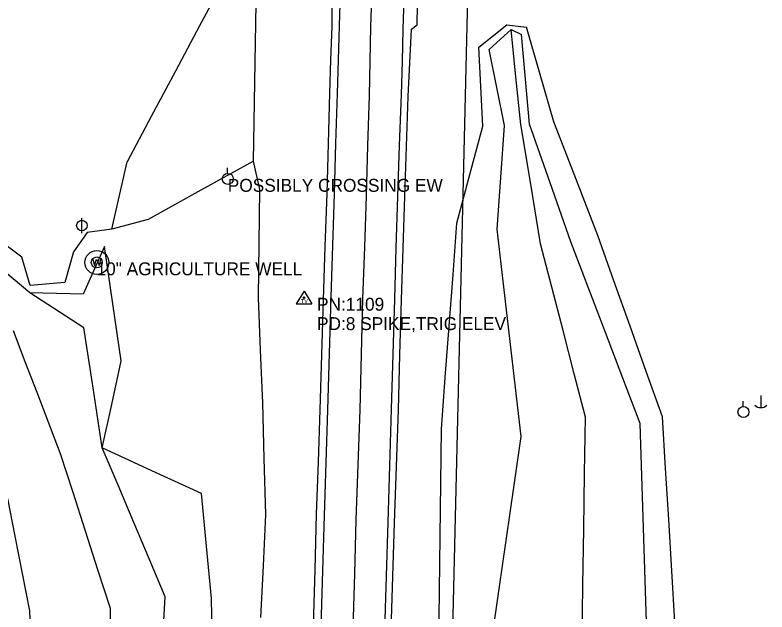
# Model space of a CAD drawing. Extents: x 1445297 to 1476720, y 2042269 to 2057889.
# Drawn here: x 1445978.9 to 1446270, y 2044535.6 to 2044766.6 of the extents above; entities that cross this region are included whole.
import ezdxf

# ---------------------------------------------------------------- set-up
doc = ezdxf.new("R2010")
doc.units = 0
for name, color, linetype in [('S_DITCHLINE', 7, 'Continuous'), ('S_EDGE_PAVEMENT', 7, 'Continuous'), ('S_PAVEMENT_CROWN', 7, 'Continuous'), ('S_SECONDARY_CTL', 7, 'Continuous'), ('S_SECONDARY_CTL_ANNOT', 7, 'Continuous'), ('S_SHOULDER', 7, 'Continuous'), ('S_STREAM', 7, 'Continuous'), ('S_UNDERGROUND_CABLE', 7, 'Continuous'), ('S_UTILITY_POLE', 7, 'Continuous'), ('S_UTILITY_POLE_ANNOT', 7, 'Continuous'), ('S_WATER_WELL', 7, 'Continuous'), ('S_WATER_WELL_ANNOT', 7, 'Continuous')]:
    doc.layers.add(name, color=color, linetype=linetype)

msp = doc.modelspace()

# ---------------------------------------------------------------- linework, layer by layer
at = {"layer": 'S_DITCHLINE'}
for points in [[(1446071.26, 2044710.05), (1446071.53, 2044725.31), (1446071.79, 2044740.57), (1446072.06, 2044755.83), (1446072.33, 2044771.09), (1446080.14, 2044771.35), (1446078.2, 2044781), (1446079.12, 2044801.93), (1446080.03, 2044822.86), (1446080.94, 2044843.78), (1446081.86, 2044864.71), (1446081.47, 2044885.83), (1446081.09, 2044906.95), (1446080.7, 2044928.07), (1446080.32, 2044949.19), (1446080.99, 2044965.26), (1446081.65, 2044981.32), (1446082.32, 2044997.38), (1446082.99, 2045013.45), (1446083.31, 2045038.44), (1446083.64, 2045063.43), (1446083.96, 2045088.42), (1446084.29, 2045113.41)], [(1446059.69, 2044779.98), (1446050.34, 2044762.42), (1446040.99, 2044744.86), (1446031.63, 2044727.3), (1446022.28, 2044709.74)], [(1446071.26, 2044710.05), (1446071.53, 2044725.31), (1446071.79, 2044740.57), (1446072.06, 2044755.83), (1446072.33, 2044771.09)], [(1446163.56, 2044524.88), (1446166.4, 2044544.53), (1446169.24, 2044564.18), (1446172.08, 2044583.82), (1446174.92, 2044603.47), (1446172.56, 2044623.53), (1446170.21, 2044643.58), (1446167.86, 2044663.63), (1446165.51, 2044683.68), (1446166.97, 2044703.75), (1446168.44, 2044723.81), (1446165.46, 2044738.52), (1446162.48, 2044753.23), (1446170.95, 2044761)], [(1446198.43, 2044524.43), (1446198.76, 2044546.08), (1446199.08, 2044567.72), (1446199.4, 2044589.36), (1446199.72, 2044611.01), (1446195.4, 2044627.76), (1446191.07, 2044644.52), (1446186.74, 2044661.28), (1446182.41, 2044678.03), (1446178.57, 2044701.13), (1446174.74, 2044724.23), (1446172.85, 2044742.61), (1446170.95, 2044761), (1446174.97, 2044759.11)], [(1446223.47, 2044527.71), (1446222.82, 2044547.92), (1446222.18, 2044568.13), (1446221.53, 2044588.33), (1446220.88, 2044608.54), (1446214.18, 2044626.13), (1446207.47, 2044643.72), (1446200.76, 2044661.31), (1446194.05, 2044678.89), (1446186.09, 2044701.62), (1446178.12, 2044724.34), (1446176.55, 2044741.73), (1446174.97, 2044759.11)], [(1446016.41, 2044683.77), (1446019.34, 2044696.75), (1446022.28, 2044709.74)], [(1446055.19, 2044527.11), (1446055, 2044540.86), (1446053.07, 2044561.15), (1446051.15, 2044581.44), (1446031.93, 2044590.26), (1446012.7, 2044599.08), (1446016.33, 2044615.93), (1446019.97, 2044632.77), (1446016.73, 2044654.89), (1446013.5, 2044677.01), (1446005.3, 2044658.54), (1445984.59, 2044659.09)], [(1446036.33, 2044527.74), (1446037.06, 2044541.54), (1446030.97, 2044555.92), (1446024.88, 2044570.31), (1446018.79, 2044584.69), (1446012.7, 2044599.08), (1446009.14, 2044622.33), (1446005.59, 2044645.59), (1445984.59, 2044659.09), (1445975.02, 2044667.24)], [(1446015.99, 2044523.36), (1446015.83, 2044536.97), (1446011.01, 2044551.93), (1446006.2, 2044566.89), (1446001.38, 2044581.86), (1445996.56, 2044596.82), (1445992.01, 2044608.7), (1445987.45, 2044620.58), (1445982.9, 2044632.46), (1445978.35, 2044644.34)], [(1445978.15, 2044367.9), (1445980.65, 2044385.13), (1445983.14, 2044402.36), (1445985.64, 2044419.58), (1445988.13, 2044436.81), (1445987.28, 2044461.63), (1445986.42, 2044486.45), (1445985.57, 2044511.27), (1445984.71, 2044536.09), (1445981.85, 2044550.56), (1445978.98, 2044565.02), (1445976.11, 2044579.49)]]:
    msp.add_lwpolyline(points, dxfattribs=at)
at = {"layer": 'S_EDGE_PAVEMENT'}
for points in [[(1446097.48, 2044530.06), (1446098.11, 2044551.51), (1446098.75, 2044572.96), (1446099.36, 2044593.42), (1446099.97, 2044613.89), (1446100.66, 2044635.63), (1446101.35, 2044657.38), (1446101.98, 2044677.4), (1446102.6, 2044697.42), (1446103.16, 2044716.83), (1446103.71, 2044736.24), (1446104.11, 2044749.29), (1446104.51, 2044762.35), (1446104.92, 2044775.04)], [(1446122.08, 2044528.6), (1446122.72, 2044549.46), (1446123.36, 2044570.32), (1446124.01, 2044592.21), (1446124.66, 2044614.1), (1446125.29, 2044635.4), (1446125.91, 2044656.7), (1446126.52, 2044676.53), (1446127.12, 2044696.37), (1446127.81, 2044716.11), (1446128.5, 2044735.85), (1446128.86, 2044748.56), (1446129.22, 2044761.27), (1446129.55, 2044772.98)], [(1446122.08, 2044528.6), (1446122.72, 2044549.46), (1446123.36, 2044570.32), (1446124.01, 2044592.21), (1446124.66, 2044614.1), (1446125.29, 2044635.4), (1446125.91, 2044656.7), (1446126.52, 2044676.53), (1446127.12, 2044696.37), (1446127.81, 2044716.11), (1446128.5, 2044735.85), (1446128.86, 2044748.56), (1446129.22, 2044761.27), (1446129.55, 2044772.98)]]:
    msp.add_lwpolyline(points, dxfattribs=at)
at = {"layer": 'S_PAVEMENT_CROWN'}
msp.add_lwpolyline([(1446109.82, 2044529.39), (1446110.41, 2044550.33), (1446111, 2044571.27), (1446111.77, 2044592.54), (1446112.53, 2044613.81), (1446113.08, 2044635.32), (1446113.62, 2044656.84), (1446114.31, 2044676.76), (1446114.99, 2044696.68), (1446115.54, 2044716.04), (1446116.09, 2044735.4), (1446116.35, 2044748.7), (1446116.61, 2044761.99), (1446117.03, 2044773.09)], dxfattribs=at)
at = {"layer": 'S_SECONDARY_CTL'}
for p, q in [((1446090.82, 2044659.8), (1446087.81, 2044654.84)), ((1446090.82, 2044659.8), (1446093.77, 2044654.84)), ((1446087.81, 2044654.84), (1446093.77, 2044654.84))]:
    msp.add_line(p, q, dxfattribs=at)
for radius in [0.311, 0.183, 0.103]:
    msp.add_circle((1446090.82, 2044657.19), radius, dxfattribs=at)
at = {"layer": 'S_SHOULDER'}
for points in [[(1446124.56, 2044528.61), (1446125.18, 2044549.35), (1446125.79, 2044570.09), (1446126.56, 2044591.96), (1446127.33, 2044613.84), (1446127.93, 2044635.14), (1446128.54, 2044656.44), (1446129.16, 2044676.39), (1446129.78, 2044696.33), (1446130.47, 2044715.72), (1446131.16, 2044735.11), (1446131.79, 2044748.1), (1446132.41, 2044761.09), (1446134.55, 2044762.73), (1446134.89, 2044777.96)], [(1446124.56, 2044528.61), (1446125.18, 2044549.35), (1446125.79, 2044570.09), (1446126.56, 2044591.96), (1446127.33, 2044613.84), (1446127.93, 2044635.14), (1446128.54, 2044656.44), (1446129.16, 2044676.39), (1446129.78, 2044696.33), (1446130.47, 2044715.72), (1446131.16, 2044735.11), (1446131.79, 2044748.1), (1446132.41, 2044761.09), (1446134.55, 2044762.73), (1446134.89, 2044777.96)], [(1446092.03, 2044445.38), (1446092.58, 2044465.83), (1446093.12, 2044486.28), (1446093.79, 2044508.32), (1446094.45, 2044530.36), (1446095.05, 2044551.93), (1446095.64, 2044573.49), (1446096.34, 2044593.67), (1446097.03, 2044613.86), (1446097.67, 2044635.16), (1446098.31, 2044656.46), (1446099.01, 2044676.99), (1446099.71, 2044697.52), (1446100.23, 2044716.92), (1446100.74, 2044736.31), (1446101.24, 2044749.26), (1446101.75, 2044762.2), (1446101.73, 2044769.88)]]:
    msp.add_lwpolyline(points, dxfattribs=at)
at = {"layer": 'S_STREAM'}
for points in [[(1446142.95, 2044523.18), (1446143.21, 2044543.98), (1446143.47, 2044564.79), (1446143.72, 2044585.59), (1446143.98, 2044606.39), (1446145.48, 2044626.32), (1446146.99, 2044646.25), (1446148.49, 2044666.18), (1446150, 2044686.11), (1446155.03, 2044704.86), (1446160.07, 2044723.61), (1446159.27, 2044738.87), (1446158.47, 2044754.12), (1446169.32, 2044762.75), (1446176.91, 2044761.92)], [(1446234.4, 2044531.71), (1446233.18, 2044551.58), (1446231.97, 2044571.45), (1446230.76, 2044591.32), (1446229.54, 2044611.19), (1446223.28, 2044628.72), (1446217.02, 2044646.26), (1446210.76, 2044663.8), (1446204.51, 2044681.34), (1446196, 2044703.3), (1446187.49, 2044725.26), (1446182.2, 2044743.59), (1446176.91, 2044761.92)], [(1446074.14, 2044533.5), (1446075.07, 2044553.43), (1446076.01, 2044573.36), (1446075.41, 2044594.95), (1446074.8, 2044616.54), (1446073.99, 2044636.91), (1446073.18, 2044657.28), (1446073.46, 2044678.15), (1446073.73, 2044699.02), (1446071.26, 2044710.05), (1446050.83, 2044698.79), (1446030.4, 2044687.53), (1446016.41, 2044683.77), (1446006.88, 2044682.5), (1446001.6, 2044674.99), (1445998.22, 2044663.07), (1445984.82, 2044661.99), (1445981.56, 2044672.84), (1445971.76, 2044680.13)]]:
    msp.add_lwpolyline(points, dxfattribs=at)
at = {"layer": 'S_UNDERGROUND_CABLE'}
msp.add_line((1446154.27, 2044781.92), (1446141.2, 2044230.61), dxfattribs=at)
at = {"layer": 'S_UTILITY_POLE'}
for p, q in [((1446061.16, 2044705.33), (1446061.16, 2044707.44)), ((1446004.8, 2044682.2), (1446004.8, 2044687.99)), ((1446267.61, 2044619.39), (1446267.61, 2044614.67)), ((1446260.82, 2044615.13), (1446260.82, 2044617.24))]:
    msp.add_line(p, q, dxfattribs=at)
for centre, radius in [((1446061.29, 2044703.19), 2.13), ((1446004.8, 2044685.13), 2.05), ((1446260.94, 2044612.99), 2.13)]:
    msp.add_circle(centre, radius, dxfattribs=at)
msp.add_arc((1446267.67, 2044618.09), 3.41, 226.3972, 313.6028, dxfattribs=at)
at = {"layer": 'S_WATER_WELL'}
for p, q in [((1446009.05, 2044672.11), (1446009.7, 2044669.63)), ((1446009.7, 2044669.63), (1446010.52, 2044672.11)), ((1446010.52, 2044672.11), (1446011.56, 2044669.63)), ((1446011.56, 2044669.63), (1446012.15, 2044672.15))]:
    msp.add_line(p, q, dxfattribs=at)
for centre, radius in [((1446010.61, 2044670.85), 4.63), ((1446010.58, 2044670.85), 2.13)]:
    msp.add_circle(centre, radius, dxfattribs=at)

# ---------------------------------------------------------------- texts
at = {"layer": 'S_SECONDARY_CTL'}
msp.add_text('TV', height=1.5, dxfattribs=at).set_placement((1446089.62, 2044655.18))
at = {"layer": 'S_SECONDARY_CTL_ANNOT'}
for s, p in [('PN:1109', (1446095.82, 2044652.19)), ('PD:8 SPIKE,TRIG ELEV', (1446095.82, 2044644.69))]:
    msp.add_text(s, height=5, dxfattribs=at).set_placement(p)
at = {"layer": 'S_UTILITY_POLE_ANNOT'}
msp.add_text('POSSIBLY CROSSING EW', height=5, dxfattribs=at).set_placement((1446061.29, 2044698.19))
at = {"layer": 'S_WATER_WELL_ANNOT'}
msp.add_text('10" AGRICULTURE WELL', height=5, dxfattribs=at).set_placement((1446010.46, 2044665.89))

doc.saveas('drawing.dxf')
